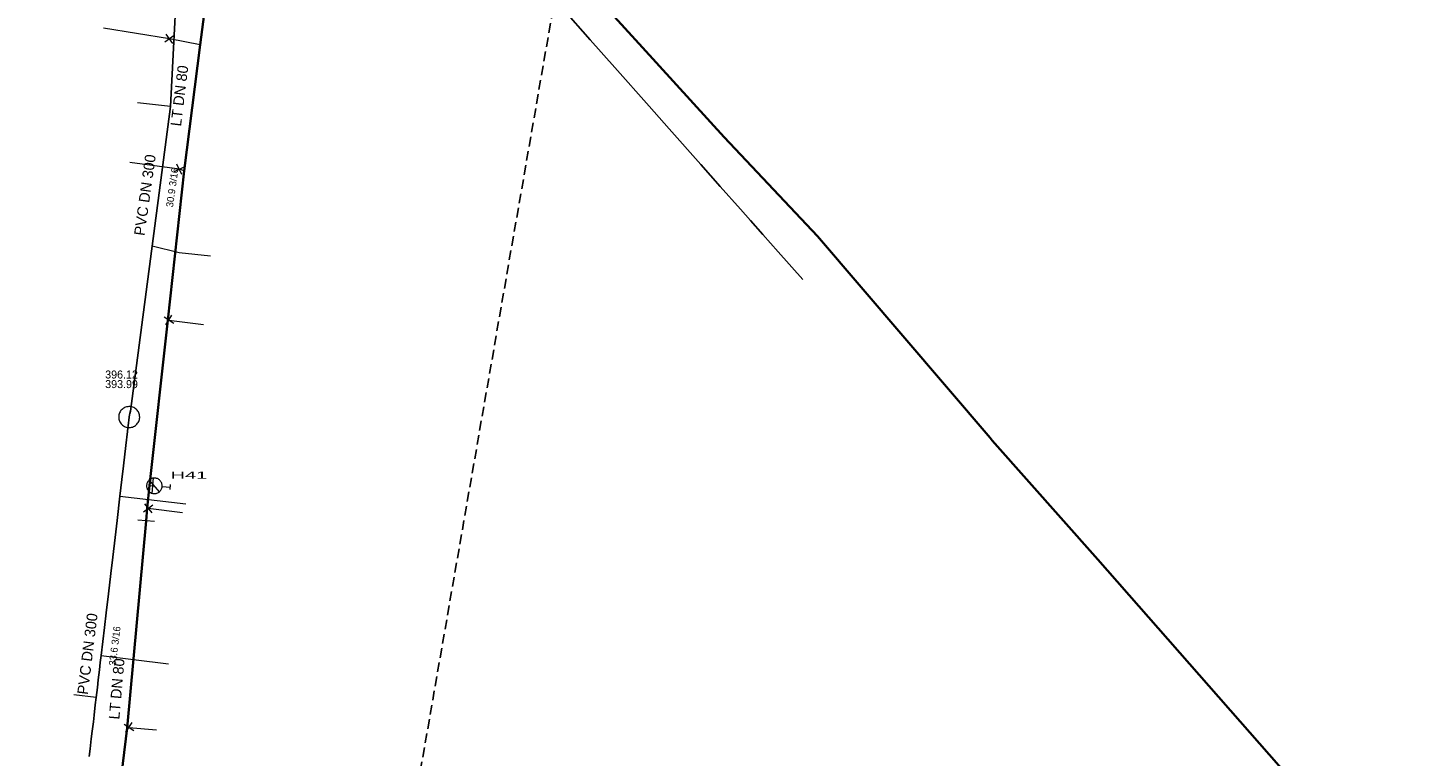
# Model space of a CAD drawing. Extents: x -772952 to -772403, y -1033777 to -1033210.
# Drawn here: x -772638.2 to -772482.8, y -1033502.9 to -1033421 of the extents above; entities that cross this region are included whole.
import ezdxf

# ---------------------------------------------------------------- set-up
doc = ezdxf.new("R2010")
doc.units = 0
doc.header["$LTSCALE"] = 0.36
doc.linetypes.add('MEDIUM_DASHED', pattern=[4.5, 3, -1.5])
for name, color, linetype, lineweight in [('15', 7, 'Continuous', 13), ('16', 7, 'Continuous', 35), ('2', 7, 'Continuous', 25), ('20', 7, 'Continuous', 13), ('4', 7, 'Continuous', 13), ('57', 7, 'Continuous', 13), ('59', 7, 'Continuous', 13), ('62', 7, 'MEDIUM_DASHED', 25)]:
    doc.layers.add(name, color=color, linetype=linetype, lineweight=lineweight)
for name, color, linetype in [('17', 7, 'Continuous'), ('3', 7, 'Continuous'), ('6', 7, 'Continuous')]:
    doc.layers.add(name, color=color, linetype=linetype)

msp = doc.modelspace()

# ---------------------------------------------------------------- linework, layer by layer
at = {"layer": '15'}
for p, q in [((-772621.742, -1033421.871), (-772622.799, -1033422.63)), ((-772621.894, -1033422.773), (-772622.645, -1033421.723)), ((-772620.859, -1033437.486), (-772621.43, -1033436.33)), ((-772620.563, -1033436.62), (-772621.729, -1033437.2)), ((-772622.676, -1033454.394), (-772621.979, -1033453.295)), ((-772622.872, -1033453.5), (-772621.784, -1033454.194)), ((-772624.209, -1033473.39), (-772624.06, -1033471.534)), ((-772625.166, -1033475.406), (-772624.143, -1033474.602)), ((-772625.053, -1033474.498), (-772624.258, -1033475.514)), ((-772623.945, -1033476.483), (-772625.801, -1033476.336)), ((-772627.36, -1033499.262), (-772626.283, -1033499.973)), ((-772627.179, -1033500.159), (-772626.464, -1033499.071))]:
    msp.add_line(p, q, dxfattribs=at)
at = {"layer": '16'}
for points in [[(-772613.548, -1033378.614), (-772617.688, -1033414.284), (-772618.8, -1033422.937), (-772620.62, -1033437.085), (-772622.445, -1033453.872), (-772624.496, -1033472.436), (-772624.78, -1033475.004), (-772624.872, -1033476.41)], [(-772612.278, -1033377.333), (-772580.497, -1033410.436), (-772578.041, -1033413.37), (-772577.006, -1033414.5), (-772569.058, -1033423.229), (-772559.875, -1033433.313), (-772549.379, -1033444.412), (-772529.995, -1033467.089), (-772529.738, -1033467.366), (-772517.883, -1033480.75), (-772495.067, -1033506.688), (-772494.015, -1033507.864), (-772482.842, -1033520.835)], [(-772624.872, -1033476.41), (-772627.006, -1033499.655), (-772628.473, -1033511.706)]]:
    msp.add_lwpolyline(points, dxfattribs=at)
at = {"layer": '2'}
for points in [[(-772621.262, -1033412.344), (-772621.314, -1033413.381), (-772621.374, -1033414.563), (-772621.814, -1033423.299), (-772622.145, -1033429.861), (-772626.646, -1033464.096), (-772626.699, -1033464.335), (-772626.739, -1033464.518), (-772626.79, -1033464.75)], [(-772584.26, -1033411.84), (-772583.281, -1033412.97), (-772582.626, -1033413.707), (-772581.458, -1033415.024), (-772577.989, -1033418.933), (-772574.948, -1033422.36), (-772572.179, -1033425.48), (-772568.334, -1033429.813), (-772566.069, -1033432.365), (-772562.501, -1033436.385), (-772560.333, -1033438.828), (-772558.052, -1033441.399), (-772556.944, -1033442.647), (-772555.536, -1033444.234), (-772553.815, -1033446.173), (-772551.058, -1033449.281)], [(-772626.79, -1033464.75), (-772626.908, -1033465.752), (-772626.934, -1033465.974), (-772626.982, -1033466.384), (-772627.164, -1033467.93), (-772627.434, -1033470.22), (-772627.615, -1033471.756), (-772627.835, -1033473.627), (-772628.156, -1033476.357), (-772628.381, -1033478.267), (-772628.645, -1033480.51), (-772628.858, -1033482.321), (-772629.13, -1033484.627), (-772629.378, -1033486.734), (-772629.572, -1033488.379), (-772629.944, -1033491.545), (-772630.035, -1033492.313), (-772630.132, -1033493.142), (-772630.264, -1033494.26), (-772630.369, -1033495.15), (-772630.5, -1033496.262), (-772630.596, -1033497.079), (-772630.733, -1033498.246), (-772630.82, -1033498.981), (-772630.946, -1033500.054), (-772631.047, -1033500.909), (-772631.177, -1033502.011), (-772631.28, -1033502.885)]]:
    msp.add_lwpolyline(points, dxfattribs=at)
at = {"layer": '20'}
for p, q in [((-772623.392, -1033473.137), (-772624.527, -1033471.805)), ((-772623.076, -1033472.542), (-772622.195, -1033472.613)), ((-772622.174, -1033472.344), (-772622.217, -1033472.883))]:
    msp.add_line(p, q, dxfattribs=at)
msp.add_lwpolyline([(-772624.029, -1033473.348), (-772623.939, -1033473.351), (-772623.848, -1033473.344), (-772623.757, -1033473.328), (-772623.67, -1033473.302), (-772623.585, -1033473.267), (-772623.504, -1033473.224), (-772623.429, -1033473.171), (-772623.358, -1033473.113), (-772623.297, -1033473.046), (-772623.241, -1033472.974), (-772623.192, -1033472.896), (-772623.151, -1033472.813), (-772623.12, -1033472.727), (-772623.099, -1033472.638), (-772623.088, -1033472.547), (-772623.084, -1033472.455), (-772623.091, -1033472.364), (-772623.108, -1033472.274), (-772623.135, -1033472.186), (-772623.17, -1033472.101), (-772623.214, -1033472.021), (-772623.264, -1033471.945), (-772623.325, -1033471.876), (-772623.39, -1033471.812), (-772623.463, -1033471.756), (-772623.542, -1033471.708), (-772623.623, -1033471.669), (-772623.711, -1033471.638), (-772623.799, -1033471.617), (-772623.891, -1033471.603), (-772623.981, -1033471.602), (-772624.072, -1033471.609), (-772624.163, -1033471.625), (-772624.25, -1033471.651), (-772624.335, -1033471.686), (-772624.416, -1033471.729), (-772624.491, -1033471.782), (-772624.562, -1033471.84), (-772624.623, -1033471.907), (-772624.679, -1033471.979), (-772624.728, -1033472.057), (-772624.769, -1033472.14), (-772624.798, -1033472.226), (-772624.821, -1033472.315), (-772624.832, -1033472.406), (-772624.836, -1033472.498), (-772624.827, -1033472.589), (-772624.812, -1033472.679), (-772624.785, -1033472.767), (-772624.75, -1033472.852), (-772624.706, -1033472.932), (-772624.656, -1033473.008), (-772624.595, -1033473.077), (-772624.53, -1033473.141), (-772624.457, -1033473.197), (-772624.378, -1033473.245), (-772624.297, -1033473.284), (-772624.209, -1033473.315), (-772624.121, -1033473.336), (-772624.031, -1033473.348)], dxfattribs=at)
at = {"layer": '4'}
msp.add_lwpolyline([(-772625.61, -1033464.75), (-772625.616, -1033464.631), (-772625.634, -1033464.514), (-772625.663, -1033464.398), (-772625.704, -1033464.287), (-772625.756, -1033464.18), (-772625.819, -1033464.079), (-772625.892, -1033463.984), (-772625.973, -1033463.898), (-772626.063, -1033463.82), (-772626.161, -1033463.751), (-772626.264, -1033463.693), (-772626.373, -1033463.646), (-772626.487, -1033463.609), (-772626.603, -1033463.584), (-772626.721, -1033463.572), (-772626.84, -1033463.571), (-772626.959, -1033463.582), (-772627.075, -1033463.605), (-772627.189, -1033463.639), (-772627.299, -1033463.685), (-772627.404, -1033463.742), (-772627.502, -1033463.809), (-772627.593, -1033463.885), (-772627.676, -1033463.97), (-772627.75, -1033464.064), (-772627.814, -1033464.164), (-772627.868, -1033464.27), (-772627.911, -1033464.381), (-772627.943, -1033464.495), (-772627.962, -1033464.613), (-772627.97, -1033464.732), (-772627.966, -1033464.85), (-772627.95, -1033464.968), (-772627.922, -1033465.084), (-772627.883, -1033465.196), (-772627.832, -1033465.304), (-772627.771, -1033465.406), (-772627.7, -1033465.502), (-772627.62, -1033465.589), (-772627.531, -1033465.669), (-772627.435, -1033465.739), (-772627.332, -1033465.799), (-772627.224, -1033465.848), (-772627.111, -1033465.886), (-772626.995, -1033465.912), (-772626.877, -1033465.927), (-772626.758, -1033465.93), (-772626.64, -1033465.921), (-772626.522, -1033465.9), (-772626.408, -1033465.867), (-772626.298, -1033465.823), (-772626.192, -1033465.768), (-772626.093, -1033465.702), (-772626, -1033465.627), (-772625.916, -1033465.543), (-772625.841, -1033465.451), (-772625.775, -1033465.352), (-772625.719, -1033465.247), (-772625.675, -1033465.137), (-772625.641, -1033465.023), (-772625.62, -1033464.906), (-772625.61, -1033464.787)], close=True, dxfattribs=at)
at = {"layer": '57'}
for p, q in [((-772622.145, -1033429.861), (-772625.86, -1033429.45)), ((-772627.835, -1033473.627), (-772620.41, -1033474.49)), ((-772629.944, -1033491.545), (-772622.38, -1033492.48)), ((-772630.5, -1033496.262), (-772633.03, -1033495.95))]:
    msp.add_line(p, q, dxfattribs=at)
msp.add_lwpolyline([(-772624.201, -1033445.501), (-772621.175, -1033446.245), (-772617.64, -1033446.62)], dxfattribs=at)
at = {"layer": '59'}
for points in [[(-772618.8, -1033422.937), (-772622.27, -1033422.25), (-772629.68, -1033421.04)], [(-772620.62, -1033437.086), (-772621.145, -1033436.91), (-772626.698, -1033436.134)], [(-772622.445, -1033453.872), (-772622.329, -1033453.846), (-772618.433, -1033454.364)], [(-772624.496, -1033472.436), (-772624.135, -1033472.463), (-772623.96, -1033472.477)], [(-772624.78, -1033475.005), (-772624.656, -1033475.005), (-772620.811, -1033475.465)], [(-772627.006, -1033499.655), (-772626.823, -1033499.617), (-772623.734, -1033499.887)]]:
    msp.add_lwpolyline(points, dxfattribs=at)
at = {"layer": '62'}
msp.add_lwpolyline([(-772641.514, -1033776.98), (-772641.529, -1033776.987), (-772951.708, -1033584.106), (-772846.395, -1033249.938), (-772562.451, -1033323.146)], close=True, dxfattribs=at)

# ---------------------------------------------------------------- texts
at = {"layer": '17'}
for rotation, p in [(83, (-772620.964, -1033432.13)), (85, (-772627.899, -1033498.769))]:
    msp.add_text('LT DN 80', height=1.2, rotation=rotation, dxfattribs=at).set_placement(p)
at = {"layer": '20', "width": 2.1}
msp.add_text('H41 ', height=0.8, dxfattribs=at).set_placement((-772622.134, -1033471.672))
at = {"layer": '3'}
for s, height, rotation, p in [('PVC DN 300', 1.2, 82, (-772625.065, -1033444.432)), ('30.9 3/16', 0.8, 82, (-772621.866, -1033441.226)), ('PVC DN 300', 1.2, 83, (-772631.446, -1033495.988)), ('33.6 3/16', 0.8, 83, (-772628.297, -1033492.736))]:
    msp.add_text(s, height=height, rotation=rotation, dxfattribs=at).set_placement(p)
at = {"layer": '6'}
for s, p in [('396.12', (-772629.488, -1033460.418)), ('393.99', (-772629.488, -1033461.495))]:
    msp.add_text(s, height=0.9, dxfattribs=at).set_placement(p)

doc.saveas('drawing.dxf')
